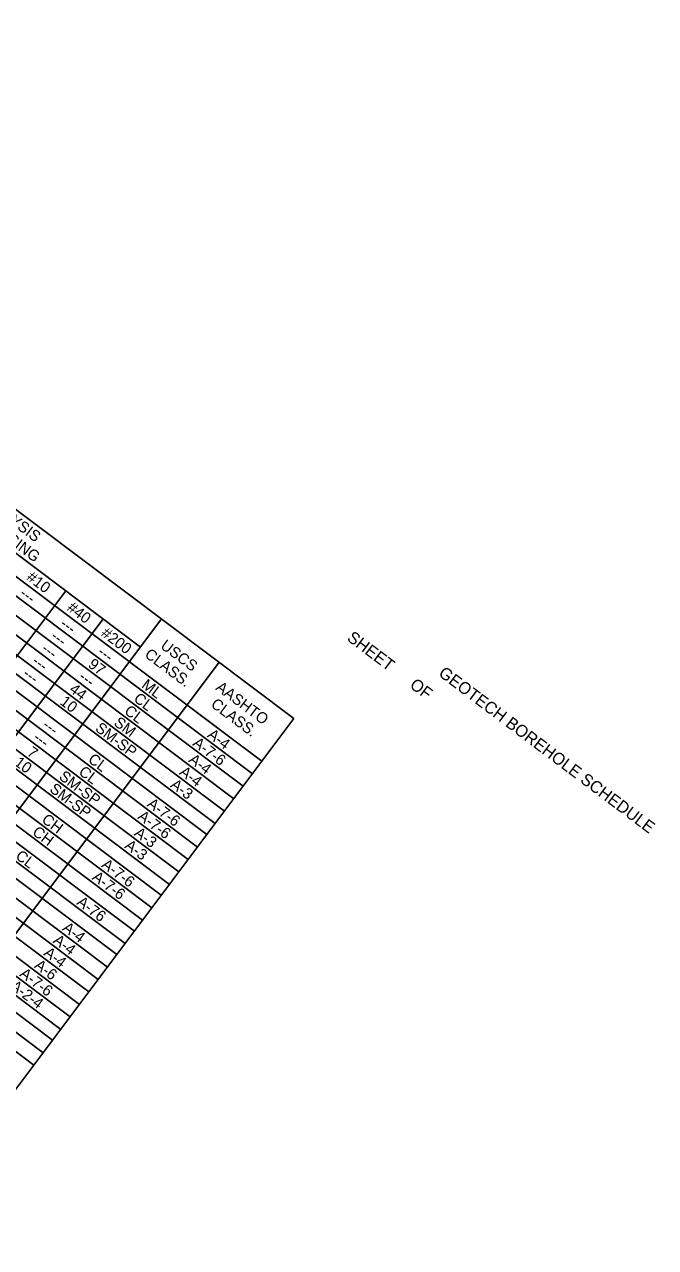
# Model space of a CAD drawing. Extents: x 627484.2 to 627514.4, y 367972.1 to 367996.9.
# Drawn here: x 627497 to 627500.16, y 367986.09 to 367992.21 of the extents above; entities that cross this region are included whole.
import ezdxf

# ---------------------------------------------------------------- set-up
doc = ezdxf.new("R2010")
doc.units = 0
for name, color, linetype in [('Default', 7, 'Continuous'), ('R_Survey Control', 7, 'Continuous'), ('R_Wall', 7, 'Continuous')]:
    doc.layers.add(name, color=color, linetype=linetype)

msp = doc.modelspace()

# ---------------------------------------------------------------- linework, layer by layer
at = {"layer": 'Default'}
for p, q in [((627493.1098, 367992.6713), (627498.3493, 367988.737)), ((627492.9488, 367992.4569), (627498.1883, 367988.5226)), ((627492.902, 367992.3945), (627498.1414, 367988.4602)), ((627492.8552, 367992.3322), (627498.0946, 367988.3978)), ((627492.8083, 367992.2698), (627498.0477, 367988.3355)), ((627492.7615, 367992.2074), (627498.0009, 367988.2731)), ((627492.7147, 367992.1451), (627497.9541, 367988.2107)), ((627492.6737, 367992.0905), (627497.9131, 367988.1562)), ((627492.6268, 367992.0281), (627497.8663, 367988.0938)), ((627492.58, 367991.9657), (627497.8194, 367988.0314)), ((627492.5332, 367991.9034), (627497.7726, 367987.969)), ((627492.4863, 367991.841), (627497.7257, 367987.9067)), ((627492.4453, 367991.7864), (627497.6848, 367987.8521)), ((627492.3985, 367991.724), (627497.6379, 367987.7897)), ((627492.3517, 367991.6617), (627497.5911, 367987.7273)), ((627492.3107, 367991.6071), (627497.5501, 367987.6728)), ((627492.2639, 367991.5447), (627497.5033, 367987.6104)), ((627492.2229, 367991.4901), (627497.4623, 367987.5558)), ((627492.176, 367991.4278), (627497.4155, 367987.4934)), ((627492.1292, 367991.3654), (627497.3686, 367987.4311)), ((627492.0824, 367991.303), (627497.3218, 367987.3687)), ((627492.0355, 367991.2406), (627497.2749, 367987.3063)), ((627491.9887, 367991.1783), (627497.2281, 367987.244)), ((627491.9419, 367991.1159), (627497.1813, 367987.1816)), ((627491.9009, 367991.0613), (627497.1403, 367987.127)), ((627491.854, 367990.999), (627497.0935, 367987.0646)), ((627491.8072, 367990.9366), (627497.0466, 367987.0023)), ((627495.9907, 367990.2886), (627497.5812, 367989.0943)), ((627495.3247, 367986.8687), (627497.2069, 367989.3753)), ((627495.5118, 367986.7282), (627497.394, 367989.2348)), ((627495.6989, 367986.5877), (627497.6865, 367989.2346)), ((627495.9874, 367986.3711), (627497.975, 367989.018)), ((627497.5255, 367989.0202), (627498.1883, 367988.5226)), ((627496.3616, 367986.0901), (627498.3493, 367988.737))]:
    msp.add_line(p, q, dxfattribs=at)

# ---------------------------------------------------------------- texts
for s, p in [('SIEVE ANALYSIS', (627496.5779, 367989.9746)), ('PERCENT PASSING', (627496.4932, 367989.935)), ('#10', (627497.0058, 367989.434)), ('---', (627496.971, 367989.3534)), ('#40', (627497.2085, 367989.2818)), ('---', (627497.1738, 367989.2012)), ('---', (627497.1269, 367989.1389)), ('#200', (627497.3794, 367989.1535)), ('USCS', (627497.6767, 367989.0916)), ('---', (627497.0801, 367989.0765)), ('---', (627497.3609, 367989.0607)), ('CLASS.', (627497.5974, 367989.0479)), ('---', (627497.0332, 367989.0141)), ('97', (627497.3142, 367988.9982)), ('---', (627496.9864, 367988.9517)), ('---', (627497.2672, 367988.936)), ('44', (627497.2202, 367988.8737)), ('ML', (627497.5818, 367988.8948)), ('AASHTO', (627497.9537, 367988.8836)), ('10', (627497.1734, 367988.8113)), ('CL', (627497.5422, 367988.827)), ('CLASS.', (627497.9288, 367988.7991)), ('CL', (627497.4954, 367988.7646)), ('---', (627497.0857, 367988.6943)), ('SM-SP', (627497.3498, 367988.6789)), ('SM', (627497.4431, 367988.7064)), ('---', (627497.0389, 367988.6319)), ('A-4', (627497.9118, 367988.647)), ('7', (627497.0084, 367988.5572)), ('A-7-6', (627497.838, 367988.6049)), ('10', (627496.945, 367988.5073)), ('CL', (627497.3139, 367988.5229)), ('A-4', (627497.8181, 367988.5223)), ('SM-SP', (627497.1683, 367988.4372)), ('CL', (627497.267, 367988.4606)), ('A-4', (627497.7713, 367988.4599)), ('SM-SP', (627497.1215, 367988.3748)), ('A-3', (627497.726, 367988.3963)), ('A-7-6', (627497.6097, 367988.3008)), ('CH', (627497.0819, 367988.2216)), ('A-7-6', (627497.5629, 367988.2384)), ('CH', (627497.0351, 367988.1592)), ('A-3', (627497.5446, 367988.1546)), ('A-3', (627497.4977, 367988.0923)), ('CL', (627496.9509, 367988.0396)), ('A-7-6', (627497.3814, 367987.9967)), ('A-7-6', (627497.3345, 367987.9344)), ('A-76', (627497.2575, 367987.8093)), ('A-4', (627497.1859, 367987.6802)), ('A-4', (627497.139, 367987.6179)), ('A-4', (627497.0922, 367987.5555)), ('A-7-6', (627496.9716, 367987.451)), ('A-6', (627497.0455, 367987.493)), ('A-2-4', (627496.9246, 367987.3887))]:
    msp.add_text(s, height=0.055, rotation=323.09678, dxfattribs=at).set_placement(p)
at = {"layer": 'R_Survey Control'}
for s, p in [('SHEET', (627498.6103, 367989.1307)), ('OF', (627498.9243, 367988.8949))]:
    msp.add_text(s, height=0.06, rotation=323.09678, dxfattribs=at).set_placement(p)
at = {"layer": 'R_Wall'}
msp.add_text('GEOTECH BOREHOLE SCHEDULE', height=0.06, rotation=323.09678, dxfattribs=at).set_placement((627499.0686, 367988.9535))

doc.saveas('drawing.dxf')
